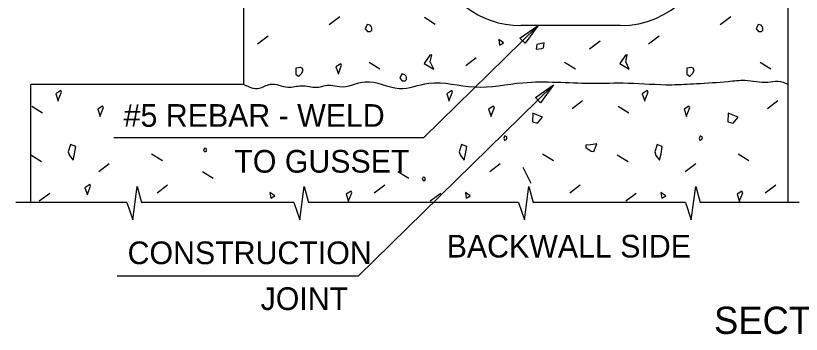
# Model space of a CAD drawing. Extents: x 0 to 22.7, y 0 to 15.7.
# Drawn here: x 5.592 to 9.202, y 4.035 to 5.499 of the extents above; entities that cross this region are included whole.
import ezdxf

# ---------------------------------------------------------------- set-up
doc = ezdxf.new("R2010")
doc.units = 0
for name, color, linetype in [('BRDG_ANNO_General-Notes', 7, 'Continuous'), ('BRDG_BASE_Obj-Line', 7, 'Continuous'), ('BRDG_BASE_Pattern', 7, 'Continuous'), ('BRDG_BASE_Rebar', 7, 'Continuous')]:
    doc.layers.add(name, color=color, linetype=linetype)

msp = doc.modelspace()

# ---------------------------------------------------------------- linework, layer by layer
at = {"layer": 'BRDG_ANNO_General-Notes'}
for p, q in [((7.4674, 4.9397), (7.9924, 5.4537)), ((7.9093, 5.3957), (7.9924, 5.4537)), ((7.9924, 5.4537), (7.9326, 5.3719)), ((7.9326, 5.3719), (7.9093, 5.3957)), ((7.1672, 4.3041), (8.0629, 5.181)), ((7.9798, 5.123), (8.0629, 5.181)), ((8.0629, 5.181), (8.0031, 5.0992)), ((8.0031, 5.0992), (7.9798, 5.123)), ((6.0429, 4.9397), (7.4674, 4.9397)), ((6.0581, 4.3041), (7.1672, 4.3041))]:
    msp.add_line(p, q, dxfattribs=at)
at = {"layer": 'BRDG_BASE_Obj-Line'}
for p, q in [((6.6404, 5.1829), (6.6404, 7.2027)), ((9.1416, 5.1829), (9.1416, 6.0371)), ((6.6404, 5.1829), (5.6612, 5.1829)), ((5.6612, 4.6412), (5.6612, 5.1829)), ((9.1416, 4.6412), (9.1416, 5.1829)), ((6.1293, 4.5604), (6.1496, 4.7137)), ((6.1496, 4.7137), (6.1703, 4.6412)), ((6.8967, 4.5604), (6.917, 4.7137)), ((6.917, 4.7137), (6.9378, 4.6412)), ((7.9293, 4.5604), (7.9496, 4.7137)), ((7.9496, 4.7137), (7.9703, 4.6412)), ((8.6967, 4.5604), (8.717, 4.7137)), ((8.717, 4.7137), (8.7378, 4.6412)), ((6.103, 4.6412), (5.5916, 4.6412)), ((6.103, 4.6412), (6.1293, 4.5604)), ((6.8705, 4.6412), (6.1703, 4.6412)), ((6.8705, 4.6412), (6.8967, 4.5604)), ((7.3916, 4.6412), (6.9378, 4.6412)), ((7.903, 4.6412), (7.3916, 4.6412)), ((7.903, 4.6412), (7.9293, 4.5604)), ((8.6705, 4.6412), (7.9703, 4.6412)), ((8.6705, 4.6412), (8.6967, 4.5604)), ((9.1916, 4.6412), (8.7378, 4.6412))]:
    msp.add_line(p, q, dxfattribs=at)
msp.add_spline([(6.6404, 5.1829), (6.7107, 5.1653), (6.7607, 5.1839), (6.8429, 5.1707), (6.9055, 5.1771), (6.9743, 5.1702), (7.0399, 5.1798), (7.0797, 5.1728), (7.1982, 5.1957), (7.3533, 5.1648), (7.4898, 5.1884), (7.6996, 5.1715), (7.9228, 5.1911), (8.2327, 5.1885), (8.4058, 5.1896), (8.6064, 5.1818), (8.7203, 5.187), (8.866, 5.1971), (8.9435, 5.2021), (9.0484, 5.1936), (9.0939, 5.1985), (9.1417, 5.1829)], degree=3, dxfattribs=at)
at = {"layer": 'BRDG_BASE_Pattern'}
for p, q in [((7.0807, 5.4931), (7.0326, 5.4565)), ((7.4705, 5.4914), (7.5199, 5.4602)), ((8.8777, 5.4931), (8.8295, 5.4565)), ((6.7516, 5.4047), (6.7035, 5.3681)), ((8.2776, 5.3817), (8.2294, 5.3451)), ((8.5485, 5.4047), (8.5004, 5.3681)), ((7.2161, 5.2856), (7.2656, 5.2544)), ((7.7078, 5.3053), (7.6596, 5.2686)), ((8.1145, 5.2856), (8.1641, 5.2544)), ((9.013, 5.2856), (9.0626, 5.2544)), ((8.1965, 5.107), (8.1484, 5.0704)), ((9.0949, 5.107), (9.0468, 5.0704)), ((5.6653, 5.083), (5.7147, 5.0519)), ((8.3607, 5.083), (8.4102, 5.0519)), ((5.6612, 4.8596), (5.7106, 4.8283)), ((6.2161, 4.8649), (6.2656, 4.8336)), ((8.0131, 4.8649), (8.0626, 4.8336)), ((8.3566, 4.8596), (8.406, 4.8283)), ((8.9116, 4.8649), (8.961, 4.8336)), ((6.0215, 4.8182), (5.9734, 4.7816)), ((7.8184, 4.8182), (7.7703, 4.7816)), ((7.9228, 4.8032), (7.9595, 4.7296)), ((8.7169, 4.8182), (8.6687, 4.7816)), ((6.4497, 4.7836), (6.4992, 4.7524)), ((7.3482, 4.7836), (7.3977, 4.7524)), ((6.2898, 4.7199), (6.2417, 4.6833)), ((7.2877, 4.7205), (7.2396, 4.6839)), ((8.1862, 4.7205), (8.1381, 4.6839)), ((9.0846, 4.7205), (9.0365, 4.6839)), ((5.7481, 4.6827), (5.7, 4.6461)), ((7.5451, 4.6827), (7.4969, 4.6461)), ((8.4435, 4.6827), (8.3954, 4.6461))]:
    msp.add_line(p, q, dxfattribs=at)
for points in [[(7.2074, 5.4582), (7.1982, 5.438), (7.209, 5.4268), (7.2222, 5.4268), (7.2277, 5.4327), (7.2277, 5.4434), (7.2258, 5.4487), (7.2201, 5.4547)], [(9.0044, 5.4582), (8.9951, 5.438), (9.0059, 5.4268), (9.0192, 5.4268), (9.0246, 5.4327), (9.0246, 5.4434), (9.0228, 5.4487), (9.017, 5.4547)], [(7.812, 5.3889), (7.8157, 5.363), (7.8342, 5.3741)], [(7.9872, 5.3664), (7.9835, 5.3443), (8.0093, 5.348), (8.0167, 5.3516), (8.0204, 5.3738)], [(7.4951, 5.3171), (7.4693, 5.2785), (7.5126, 5.2526), (7.4968, 5.2876), (7.5035, 5.3197)], [(8.3935, 5.3171), (8.3678, 5.2785), (8.4111, 5.2526), (8.3953, 5.2876), (8.4019, 5.3197)], [(7.0632, 5.2636), (7.0745, 5.2304), (7.0745, 5.234), (7.0893, 5.271), (7.0856, 5.2783)], [(6.8788, 5.2576), (6.8788, 5.2296), (6.8914, 5.2207), (6.8953, 5.2243), (6.9061, 5.2354), (6.9135, 5.2502), (6.9081, 5.2576), (6.9007, 5.2611), (6.8971, 5.2611), (6.8899, 5.2591)], [(8.6757, 5.2576), (8.6757, 5.2296), (8.6883, 5.2207), (8.6922, 5.2243), (8.703, 5.2354), (8.7104, 5.2502), (8.7051, 5.2576), (8.6977, 5.2611), (8.6941, 5.2611), (8.6868, 5.2591)], [(7.3668, 5.2314), (7.3576, 5.2111), (7.3684, 5.1999), (7.3816, 5.1999), (7.387, 5.2058), (7.387, 5.2166), (7.3852, 5.2219), (7.3795, 5.2278)], [(5.7761, 5.1398), (5.7875, 5.1066), (5.7875, 5.1101), (5.8022, 5.1471), (5.7985, 5.1545)], [(7.573, 5.1398), (7.5844, 5.1066), (7.5844, 5.1101), (7.5992, 5.1471), (7.5954, 5.1545)], [(8.4715, 5.1398), (8.4829, 5.1066), (8.4829, 5.1101), (8.4977, 5.1471), (8.4939, 5.1545)], [(5.9683, 5.0691), (5.9797, 5.0359), (5.9797, 5.0394), (5.9944, 5.0765), (5.9907, 5.0838)], [(7.7652, 5.0691), (7.7766, 5.0359), (7.7766, 5.0394), (7.7914, 5.0765), (7.7876, 5.0838)], [(8.6637, 5.0691), (8.6751, 5.0359), (8.6751, 5.0394), (8.6898, 5.0765), (8.686, 5.0838)], [(7.9683, 5.0504), (7.9665, 5.0108), (7.9904, 5.0053), (8.0134, 5.032)], [(8.8667, 5.0504), (8.8649, 5.0108), (8.8889, 5.0053), (8.9119, 5.032)], [(7.8348, 4.9367), (7.8377, 4.9274), (7.8404, 4.9274), (7.8441, 4.9283), (7.8468, 4.931), (7.8495, 4.9367), (7.8487, 4.9421), (7.8441, 4.9431), (7.8421, 4.945), (7.8385, 4.945)], [(8.7332, 4.9367), (8.7361, 4.9274), (8.7388, 4.9274), (8.7426, 4.9283), (8.7453, 4.931), (8.748, 4.9367), (8.7472, 4.9421), (8.7426, 4.9431), (8.7406, 4.945), (8.7369, 4.945)], [(5.8441, 4.9064), (5.8329, 4.8732), (5.8386, 4.8566), (5.8551, 4.8345), (5.8624, 4.864), (5.868, 4.8972)], [(6.4586, 4.89), (6.454, 4.8798), (6.4594, 4.8742), (6.466, 4.8742), (6.4688, 4.8772), (6.4688, 4.8826), (6.4679, 4.8853), (6.465, 4.8882)], [(7.641, 4.9064), (7.6298, 4.8732), (7.6355, 4.8566), (7.652, 4.8345), (7.6594, 4.864), (7.6649, 4.8972)], [(8.2344, 4.9063), (8.2123, 4.9044), (8.2123, 4.8934), (8.2363, 4.8769), (8.2493, 4.875), (8.2621, 4.9099)], [(8.5395, 4.9064), (8.5283, 4.8732), (8.534, 4.8566), (8.5505, 4.8345), (8.5579, 4.864), (8.5634, 4.8972)], [(7.4639, 4.7576), (7.4592, 4.7474), (7.4646, 4.7418), (7.4713, 4.7418), (7.474, 4.7447), (7.474, 4.7502), (7.4731, 4.7528), (7.4703, 4.7558)], [(5.9095, 4.7083), (5.9209, 4.6751), (5.9209, 4.6786), (5.9357, 4.7157), (5.9319, 4.723)], [(6.7599, 4.6864), (6.7636, 4.6606), (6.7821, 4.6717)], [(7.1104, 4.6784), (7.1218, 4.6452), (7.1218, 4.6487), (7.1365, 4.6857), (7.1327, 4.6931)], [(7.6584, 4.6864), (7.6621, 4.6606), (7.6806, 4.6717)], [(8.5568, 4.6864), (8.5605, 4.6606), (8.579, 4.6717)], [(8.9073, 4.6784), (8.9187, 4.6452), (8.9187, 4.6487), (8.9334, 4.6857), (8.9296, 4.6931)]]:
    msp.add_lwpolyline(points, close=True, dxfattribs=at)
at = {"layer": 'BRDG_BASE_Rebar'}
msp.add_line((8.3708, 5.4537), (7.9124, 5.4537), dxfattribs=at)
for centre, start, end in [((7.9124, 5.8704), 120.0007, 270), ((8.3708, 5.8704), 270, 360)]:
    msp.add_arc(centre, 0.4167, start, end, dxfattribs=at)

# ---------------------------------------------------------------- texts
at = {"layer": 'BRDG_ANNO_General-Notes'}
for s, height, p in [('#5 REBAR - WELD', 0.104167, (6.0878, 4.9883)), ('TO GUSSET', 0.10417, (6.5963, 4.7777)), ('BACKWALL SIDE', 0.104167, (7.5724, 4.3878)), ('CONSTRUCTION', 0.104167, (6.1058, 4.3573)), ('JOINT', 0.10417, (6.7172, 4.1467)), ('SECTION A-A', 0.125, (8.8011, 4.0369))]:
    msp.add_text(s, height=height, dxfattribs=at).set_placement(p)

doc.saveas('drawing.dxf')
